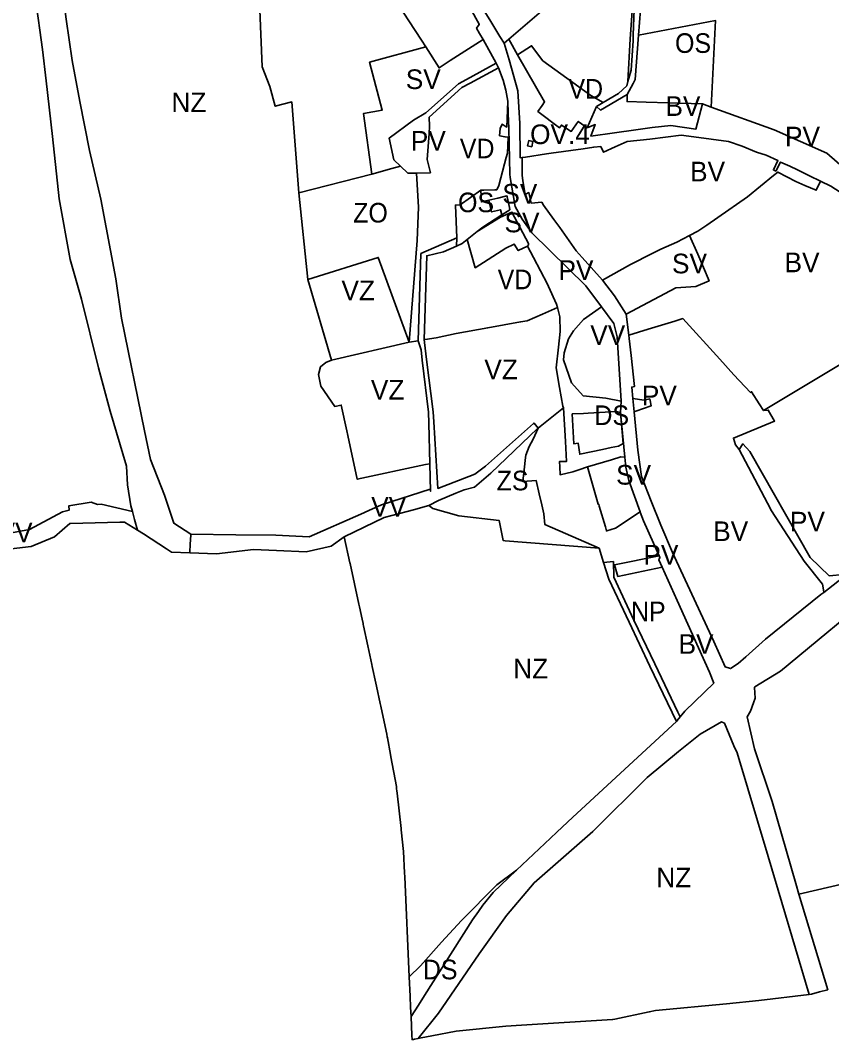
# Model space of a CAD drawing. Extents: x -650451 to -642268, y -1075216 to -1066610.
# Drawn here: x -645357 to -644737, y -1073665 to -1072886 of the extents above; entities that cross this region are included whole.
import ezdxf

# ---------------------------------------------------------------- set-up
doc = ezdxf.new("R2010")
doc.units = 0
doc.header["$LTSCALE"] = 6
doc.layers.add('1', color=7, linetype='Continuous', lineweight=35)
doc.layers.add('2', color=7, linetype='Continuous')
doc.layers.add('3', color=7, linetype='Continuous')

msp = doc.modelspace()

# ---------------------------------------------------------------- linework, layer by layer
at = {"layer": '1'}
for p, q in [((-645003.44, -1072900.56), (-644993.68, -1072918.61)), ((-644983.93, -1072900.24), (-644987.58, -1072903.38)), ((-644977.16, -1072912.11), (-644983.93, -1072900.24)), ((-644993.68, -1072918.61), (-644991.77, -1072922.13)), ((-644911.87, -1072948.76), (-644916.82, -1072951.76)), ((-644916.82, -1072951.76), (-644924, -1072967.87)), ((-644835.99, -1072949.74), (-644829.3, -1072952.16)), ((-645327.554, -1073022.214), (-645332.517, -1072974.538)), ((-645088.62, -1073003.45), (-645144.37, -1073017.64)), ((-645015.71, -1073053.41), (-645007.99, -1073047.31)), ((-645023.6, -1073052.12), (-645023.88, -1073058.37)), ((-645297.395, -1073151.294), (-645310.558, -1073098.946)), ((-644892.14, -1073126.36), (-644894.15, -1073110.3)), ((-644888.14, -1073184.92), (-644889.09, -1073174.81)), ((-644898.05, -1073176.78), (-644898.52, -1073185.53)), ((-644898.52, -1073185.53), (-644895.36, -1073219.51)), ((-645271.52, -1073261.16), (-645272.747, -1073256.762)), ((-644911.461, -1073299.98), (-644914.85, -1073289.05)), ((-644977.924, -1073535.072), (-644993.044, -1073546.324)), ((-644993.044, -1073546.324), (-645020.11, -1073573.585))]:
    msp.add_line(p, q, dxfattribs=at)
for points in [[(-645213.34, -1072669.98), (-645174.13, -1072877.93), (-645172.28, -1072921.42), (-645166.48, -1072936.5), (-645162.379, -1072951.55), (-645149.84, -1072948.13), (-645144.37, -1073017.64)], [(-645338.538, -1072746.821), (-645338.023, -1072755.969), (-645333.718, -1072799.987), (-645327.091, -1072848.387), (-645322.284, -1072885.085), (-645317.65, -1072916.642), (-645311.772, -1072947.945), (-645304.24, -1072985.372), (-645295.788, -1073022.556), (-645284.269, -1073083.286), (-645279.878, -1073113.356), (-645262.388, -1073199.409), (-645257.842, -1073221.36), (-645247.051, -1073248.736), (-645239.9, -1073270.025), (-645226.847, -1073278.345)], [(-644899.2, -1072762.14), (-644898.29, -1072766.55), (-644901.35, -1072785.36), (-644902.18, -1072797.88), (-644889.11, -1072871.66), (-644891.2, -1072900.09), (-644892.86, -1072932.6)], [(-644983.93, -1072900.24), (-644955.49, -1072875.78), (-644969.93, -1072861.43), (-644972.28, -1072859.02), (-644959.24, -1072844.92), (-644945.2, -1072826.3), (-644920.46, -1072792.92), (-644940.8, -1072781.48)], [(-645353.86, -1072794.339), (-645350.822, -1072830.388), (-645340.345, -1072908.029), (-645337.34, -1072932.073), (-645332.517, -1072974.538)], [(-645055.76, -1072816.4), (-645039.21, -1072842.26), (-645035.06, -1072848.67), (-645027.47, -1072860.37), (-645016.06, -1072878.67), (-645013.89, -1072877.29), (-645013.11, -1072876.8), (-645006.5, -1072888.88), (-645006.58, -1072889), (-645008.52, -1072891.76), (-645006.19, -1072895.8), (-645003.44, -1072900.56)], [(-645047.42, -1072906.05), (-645050.6, -1072901.03), (-645069.55, -1072872.12), (-645079.81, -1072855.89), (-645084.47, -1072825.67)], [(-644987.58, -1072903.38), (-644990.66, -1072898.22), (-644998.3, -1072885.43), (-645007.8, -1072870.27)], [(-644892.86, -1072932.6), (-644890.48, -1072924.04), (-644888.92, -1072901.64), (-644888.76, -1072897.07), (-644888.06, -1072877.6), (-644883.16, -1072877.92), (-644884.712, -1072897.147)], [(-644829.3, -1072952.16), (-644825.855, -1072886.074), (-644884.712, -1072897.147)], [(-645047.42, -1072906.05), (-645037.2, -1072922.24), (-645028.68, -1072916.54), (-645003.44, -1072900.56)], [(-644893.37, -1072942.61), (-644888.99, -1072934), (-644887.44, -1072930.94), (-644884.712, -1072897.147)], [(-645088.62, -1073003.45), (-645095.04, -1072957.07), (-645080.61, -1072954.43), (-645083.13, -1072944.94), (-645090.34, -1072917.86), (-645047.42, -1072906.05)], [(-644987.58, -1072903.38), (-644983.58, -1072915.92), (-644976.98, -1072939.7), (-644975.5, -1072964.62), (-644975.26, -1072990.9), (-644973.78, -1072990.67)], [(-644977.16, -1072912.11), (-644966.57, -1072905.23), (-644957.79, -1072916.73), (-644921.18, -1072943.17), (-644911.87, -1072948.76)], [(-644977.16, -1072912.11), (-644956.61, -1072948.16), (-644958.49, -1072950.87), (-644961.62, -1072955.39), (-644945.06, -1072967.89), (-644943.65, -1072965.85), (-644936.25, -1072970.76), (-644930.9, -1072963.08), (-644924, -1072967.87)], [(-645066.66, -1072997.3), (-645071.72, -1072992.52), (-645075.22, -1072975.8), (-645056.81, -1072962.13), (-645047.23, -1072956.57), (-645022.4, -1072934.31), (-645016.37, -1072931.01), (-644993.68, -1072918.61)], [(-644991.77, -1072922.13), (-645013.51, -1072933.92), (-645019.73, -1072937.29), (-645044.77, -1072959.83), (-645044.68, -1072961.82), (-645044.54, -1072964.66), (-645044.44, -1072966.73), (-645044.8, -1072972.22), (-645046.36, -1072992.1), (-645043.77, -1073002.3), (-645054.44, -1073002.54)], [(-644991.77, -1072922.13), (-644988.28, -1072931.51), (-644986.2, -1072939.16), (-644984.73, -1072947.56)], [(-644892.86, -1072932.6), (-644893.77, -1072935.88), (-644900.2, -1072941.67), (-644911.87, -1072948.76)], [(-645005.31, -1073015.68), (-645003.08, -1073015.61), (-644994.67, -1073015.36), (-644993.15, -1073015.31), (-644991.51, -1073012.16), (-644987.13, -1072995.44), (-644985.86, -1072990.55), (-644985.02, -1072987.36), (-644984.44, -1072975.19), (-644984.98, -1072975.1), (-644986.95, -1072974.75), (-644990.81, -1072974.08), (-644991.01, -1072974.02), (-644990.62, -1072968.58), (-644989.11, -1072965.25), (-644985.85, -1072967.18), (-644985.43, -1072967.43), (-644984.73, -1072947.56)], [(-644984.73, -1072947.56), (-644984.31, -1072957.08), (-644984, -1072968.31), (-644983.04, -1073003.33), (-644982.96, -1073006.06), (-644979.09, -1073027.97), (-644973.73, -1073037.82), (-644966.21, -1073048.32), (-644925.03, -1073088.75), (-644912.99, -1073104.65)], [(-644916.82, -1072951.76), (-644913.74, -1072954.38), (-644893.37, -1072942.61)], [(-644893.37, -1072942.61), (-644893.59, -1072947.97), (-644878.86, -1072948.42), (-644861.93, -1072948.94), (-644835.99, -1072949.74)], [(-644924, -1072967.87), (-644917.86, -1072965.55), (-644921.14, -1072974.47), (-644903.12, -1072971.8), (-644886.87, -1072969.46), (-644874.37, -1072967.75), (-644860.15, -1072966.28), (-644841.02, -1072969.02), (-644835.99, -1072949.74)], [(-644829.3, -1072952.16), (-644781.05, -1072969.61), (-644740.95, -1072987.23), (-644666.64, -1073051.97), (-644614.48, -1073096.25), (-644529.95, -1073158.06)], [(-644973.78, -1072990.67), (-644971.09, -1072990.31), (-644955.05, -1072987.8), (-644951.46, -1072987.25), (-644927.21, -1072984.16), (-644918.97, -1072982.7), (-644913.69, -1072982.13), (-644911.43, -1072986.59), (-644902.55, -1072982.55), (-644893.57, -1072978.46), (-644876.19, -1072976.67), (-644852.26, -1072973.62), (-644842.54, -1072974.93), (-644816.11, -1072978.51), (-644805.65, -1072981.92), (-644794.55, -1072986.49), (-644787.18, -1072988.95), (-644778.28, -1072993.06), (-644781.75, -1073000.11), (-644779.89, -1073001.07), (-644776.22, -1072994.18), (-644769.25, -1072997.23), (-644763.35, -1072999.96), (-644754.16, -1073004.6), (-644745.73, -1073008.64)], [(-644912.36, -1073084.42), (-644918.82, -1073077.02), (-644927.92, -1073066.94), (-644932.48, -1073061.9), (-644944.96, -1073044.2), (-644949.4, -1073038.05), (-644957.31, -1073027.07), (-644958.75, -1073024.7), (-644966.71, -1073025.57), (-644968.59, -1073017.44), (-644971.33, -1073018.81), (-644973.27, -1073008.52), (-644973.77, -1073004.25), (-644973.78, -1072990.67)], [(-645066.66, -1072997.3), (-645073.23, -1072999.05), (-645088.62, -1073003.45)], [(-645054.44, -1073002.54), (-645060.95, -1073002.68), (-645066.66, -1072997.3)], [(-645060.1, -1073131.68), (-645053.83, -1073054.04), (-645052.94, -1073028.58), (-645054.44, -1073002.54)], [(-644745.73, -1073008.64), (-644748.95, -1073015.64), (-644757.73, -1073012.05), (-644764.69, -1073008.87), (-644778.38, -1073001.84), (-644781.52, -1073004.39), (-644801.54, -1073020.61), (-644824.08, -1073036.56), (-644832.7, -1073042.34), (-644839.47, -1073046.89), (-644845.72, -1073050.14)], [(-644762.37, -1073553.42), (-644764.68, -1073545.3), (-644782.57, -1073482.57), (-644796.05, -1073442.48), (-644801.88, -1073417.95), (-644799.16, -1073413.58), (-644797.05, -1073407.39), (-644795.76, -1073403.59), (-644796.12, -1073395.56), (-644795.99, -1073395.08), (-644776.32, -1073383.08), (-644698.13, -1073318.48), (-644678.02, -1073303.11), (-644577.34, -1073226.12), (-644547.27, -1073203.12), (-644510.49, -1073173.7), (-644488.53, -1073156.12), (-644412.36, -1073110.27), (-644251.67, -1073006.23)], [(-644745.73, -1073008.64), (-644737.88, -1073012.62), (-644714.42, -1073027.62), (-644684.09, -1073050.8), (-644680.69, -1073053.67), (-644625.26, -1073099.51), (-644649.7, -1073116.65), (-644654.61, -1073120.1)], [(-645119.34, -1073145.61), (-645137.5, -1073083.97), (-645144.37, -1073017.64)], [(-645005.31, -1073015.68), (-645021.1, -1073026.69), (-645024.71, -1073026.95), (-645023.6, -1073052.12)], [(-644999.23, -1073023.29), (-645004.82, -1073024.63), (-645005.31, -1073015.68)], [(-645327.554, -1073022.214), (-645319.052, -1073068.6), (-645310.558, -1073098.946)], [(-644989.34, -1073034.58), (-644983.16, -1073030.56), (-644983.51, -1073028.9), (-644985.25, -1073020.72), (-644985.41, -1073019.98), (-644992.27, -1073021.63), (-644999.23, -1073023.29)], [(-644989.34, -1073034.58), (-644990.25, -1073030.54), (-644997.09, -1073032.21), (-644999.23, -1073023.29)], [(-645007.99, -1073047.31), (-644990.29, -1073036.36), (-644981.57, -1073032.3), (-644968.89, -1073056.23), (-644968.86, -1073057.45), (-644969.56, -1073058.48)], [(-645007.99, -1073047.31), (-645003.78, -1073043.96), (-644989.34, -1073034.58)], [(-644845.72, -1073050.14), (-644855.6, -1073055.26), (-644867.8, -1073060.76), (-644874.45, -1073064.02), (-644890.89, -1073072.33), (-644912.36, -1073084.42)], [(-644894.15, -1073110.3), (-644856.4, -1073090.13), (-644840.89, -1073089.3), (-644830.81, -1073084.98), (-644839.57, -1073064.5), (-644845.72, -1073050.14)], [(-645053.19, -1073130.59), (-645051.1, -1073064.11), (-645023.6, -1073052.12)], [(-645048.61, -1073129.7), (-645046.59, -1073065.77), (-645033.89, -1073062.8), (-645023.88, -1073058.37)], [(-645023.88, -1073058.37), (-645019.57, -1073056.46), (-645015.71, -1073053.41)], [(-645015.71, -1073053.41), (-645009.53, -1073074.93), (-644986.06, -1073059.87), (-644979.8, -1073056.82), (-644976.65, -1073061.82), (-644969.56, -1073058.48)], [(-644946.7, -1073105.33), (-644947.44, -1073102.73), (-644953.59, -1073089.19), (-644954.39, -1073087.42), (-644964.98, -1073067.05), (-644969.56, -1073058.48)], [(-645137.5, -1073083.97), (-645083.681, -1073066.962), (-645060.1, -1073131.68)], [(-644894.15, -1073110.3), (-644903.22, -1073096.43), (-644912.36, -1073084.42)], [(-644912.99, -1073104.65), (-644926.77, -1073114.52), (-644934.41, -1073123.05), (-644938.32, -1073129.23), (-644941.63, -1073139.89), (-644942.07, -1073145.31), (-644936.06, -1073162.79), (-644927.05, -1073172.62), (-644909.83, -1073174.51), (-644898.05, -1073176.78)], [(-644912.99, -1073104.65), (-644903.72, -1073117.41), (-644901.2, -1073127.58), (-644898.05, -1073176.78)], [(-645048.61, -1073129.7), (-645047.73, -1073129.58), (-645039.47, -1073128.42), (-645024.04, -1073125.1), (-645000.03, -1073120.76), (-644974.89, -1073116.24), (-644969.91, -1073115.34), (-644958.27, -1073110.25), (-644946.7, -1073105.33)], [(-644946.7, -1073105.33), (-644945, -1073112.3), (-644944.63, -1073123.59), (-644945.99, -1073135.51), (-644947.8, -1073151.31), (-644945.13, -1073166.37), (-644942.58, -1073180.69), (-644942.17, -1073181.78)], [(-644789.31, -1073183.93), (-644663.17, -1073108.27), (-644656.56, -1073117.4), (-644654.61, -1073120.1)], [(-644892.14, -1073126.36), (-644877.32, -1073121.83), (-644856.97, -1073115.6), (-644851, -1073113.77), (-644822.62, -1073144.71), (-644811.96, -1073156.75), (-644799.26, -1073170.13), (-644798.38, -1073169.56), (-644792.59, -1073178.73), (-644789.31, -1073183.93)], [(-644889.09, -1073174.81), (-644889.93, -1073166), (-644887.77, -1073165.6), (-644890.43, -1073142), (-644891.87, -1073128.85), (-644892.14, -1073126.36)], [(-645119.34, -1073145.61), (-645060.1, -1073131.68), (-645053.19, -1073130.59)], [(-645053.19, -1073130.59), (-645052.45, -1073132.97), (-645050.98, -1073137.65), (-645050.1, -1073145.42), (-645045.31, -1073185.17), (-645045.08, -1073193.68), (-645044.246, -1073224.619)], [(-645048.61, -1073129.7), (-645048.32, -1073132.07), (-645046.72, -1073145.03), (-645041.81, -1073184.95), (-645041.32, -1073192.66), (-645038.11, -1073243.46), (-645010, -1073232.5), (-645001.8, -1073226.39), (-644965.03, -1073193.94), (-644964.55, -1073193.54), (-644961.44, -1073197.35)], [(-645297.395, -1073151.294), (-645288.647, -1073184.518), (-645276.125, -1073226.571), (-645275.269, -1073240.71), (-645272.747, -1073256.762)], [(-645119.34, -1073145.61), (-645123.616, -1073147.195), (-645127.781, -1073150.527), (-645129.447, -1073156.525), (-645127.615, -1073165.356), (-645116.951, -1073180.851), (-645111.98, -1073179.822), (-645107.76, -1073199.45), (-645107.02, -1073202.91), (-645099.78, -1073236.52), (-645047.59, -1073225.3), (-645044.246, -1073224.619)], [(-644889.09, -1073174.81), (-644880.45, -1073176.07), (-644876.22, -1073175.09), (-644875.1, -1073180.36), (-644886.75, -1073184.43), (-644888.14, -1073184.92)], [(-644961.44, -1073197.35), (-644959.91, -1073196.15), (-644942.17, -1073181.78)], [(-644923.88, -1073227.01), (-644930.46, -1073229.16), (-644934.87, -1073230.72), (-644944.7, -1073233.01), (-644945.03, -1073226.98), (-644945.25, -1073223.01), (-644939.95, -1073223), (-644940.47, -1073207.57), (-644942.17, -1073181.78)], [(-644888.14, -1073184.92), (-644885.36, -1073214.3), (-644882.44, -1073234.39), (-644875.09, -1073253.22), (-644867.69, -1073271.42), (-644858.88, -1073292.32), (-644855.75, -1073299.15), (-644827.23, -1073360.35), (-644818.67, -1073379.69), (-644814.49, -1073381.06), (-644808.69, -1073377.3), (-644802.84, -1073372.09), (-644787.75, -1073358.68), (-644745.44, -1073324.48), (-644743.23, -1073322.94)], [(-644808.01, -1073213.67), (-644810.56, -1073210.15), (-644812.29, -1073205.05), (-644780.87, -1073191.97), (-644785.72, -1073183.67), (-644789.31, -1073183.93)], [(-644961.44, -1073197.35), (-644961.91, -1073197.75), (-644997.71, -1073231.77), (-645010.2, -1073242.6), (-645017.98, -1073244.63), (-645024.51, -1073247.07), (-645037.53, -1073252.62), (-645045, -1073256.54)], [(-644961.44, -1073197.35), (-644965.42, -1073205.74), (-644968.33, -1073211.34), (-644970.84, -1073218.02), (-644971.04, -1073219.75), (-644972.09, -1073229.15), (-644973.32, -1073238.15), (-644963.08, -1073237.3), (-644960.75, -1073247.57), (-644958.74, -1073256.06), (-644957.14, -1073262.81), (-644956.39, -1073270.99), (-644914.85, -1073289.05)], [(-644725.21, -1073308.93), (-644728.18, -1073309.21), (-644738.99, -1073310.21), (-644753.67, -1073296.24), (-644799.84, -1073215.22), (-644805.08, -1073209.3), (-644808.01, -1073213.67)], [(-644808.01, -1073213.67), (-644786.28, -1073254.69), (-644783.14, -1073260.62), (-644758.33, -1073299.16), (-644744.17, -1073316.51), (-644743.51, -1073321), (-644743.23, -1073322.94)], [(-644923.88, -1073227.01), (-644905.47, -1073221.56), (-644898.37, -1073219.42), (-644895.36, -1073219.51)], [(-644895.36, -1073219.51), (-644894.44, -1073227.29), (-644892.09, -1073237.34), (-644883.55, -1073261.27)], [(-645226.847, -1073278.345), (-645192.45, -1073278.84), (-645161.91, -1073279.24), (-645136.55, -1073280.36), (-645096.96, -1073263.01), (-645090.9, -1073260.31), (-645081.07, -1073256.01), (-645043.97, -1073244.09), (-645043.68, -1073245.61), (-645044.246, -1073224.619)], [(-644883.55, -1073261.27), (-644902.28, -1073273.73), (-644909.03, -1073275.83), (-644909.38, -1073275.94), (-644910.11, -1073272.74), (-644914.78, -1073257.12), (-644915.24, -1073255.45), (-644915.63, -1073255.56), (-644923.88, -1073227.01)], [(-645271.52, -1073261.16), (-645295.44, -1073255.48), (-645298.27, -1073255.65), (-645302.963, -1073253.878), (-645320.244, -1073256.876), (-645319.96, -1073260.12), (-645325.07, -1073261.39), (-645350.08, -1073274.88), (-645389.08, -1073281.94), (-645404.03, -1073288.01), (-645427.83, -1073301.03), (-645457.38, -1073313.78), (-645476.1, -1073316.93), (-645499.41, -1073318.24)], [(-645109.6, -1073280.56), (-645079.12, -1073265.63), (-645061.7, -1073261.22), (-645056.82, -1073259.85), (-645045, -1073256.54)], [(-645045, -1073256.54), (-645042.08, -1073258.81), (-645022.07, -1073264.52), (-644991.26, -1073268.06), (-644988.14, -1073283.32), (-644986.64, -1073283.44), (-644914.85, -1073289.05)], [(-645271.52, -1073261.16), (-645269.83, -1073267.22), (-645267.53, -1073275.44)], [(-644883.55, -1073261.27), (-644883.45, -1073261.55), (-644880.99, -1073268.25), (-644868.95, -1073294.94)], [(-645499.41, -1073318.24), (-645492.7, -1073323.51), (-645492.16, -1073323.95), (-645459.78, -1073326.21), (-645442.26, -1073319.33), (-645431.37, -1073313.2), (-645414.6, -1073312.83), (-645381.21, -1073286.79), (-645364.15, -1073289.58), (-645348.9, -1073287.85), (-645331.05, -1073280.34), (-645319.42, -1073270.28), (-645318.94, -1073270.27), (-645281.1, -1073269.26), (-645277.57, -1073269.17), (-645267.53, -1073275.44)], [(-645227.744, -1073292.736), (-645241.72, -1073292.2), (-645245.5, -1073289.73), (-645263.03, -1073278.25), (-645267.53, -1073275.44)], [(-645226.847, -1073278.345), (-645227.199, -1073283.366), (-645227.35, -1073285.55), (-645227.744, -1073292.736)], [(-645227.744, -1073292.736), (-645207.27, -1073293.52), (-645179.11, -1073290.25), (-645161.51, -1073290.8), (-645138.82, -1073291.94), (-645119.56, -1073287.5), (-645109.6, -1073280.56)], [(-645060.01, -1073616.531), (-645063.42, -1073540.09), (-645063.55, -1073537.04), (-645064.28, -1073520.73), (-645066.11, -1073504.38), (-645066.22, -1073503.38), (-645069.27, -1073476.16), (-645069.45, -1073474.51), (-645069.63, -1073472.94), (-645069.82, -1073471.22), (-645074, -1073448.52), (-645074.34, -1073446.7), (-645076.69, -1073433.94), (-645076.81, -1073433.27), (-645077.19, -1073431.24), (-645078.27, -1073425.38), (-645081.62, -1073409.9), (-645082.11, -1073407.66), (-645084.96, -1073394.48), (-645085.46, -1073392.18), (-645088.22, -1073379.41), (-645088.5, -1073378.1), (-645091.62, -1073363.7), (-645094.92, -1073348.42), (-645095.12, -1073347.53), (-645095.32, -1073346.61), (-645096.01, -1073343.4), (-645098.07, -1073333.86), (-645098.51, -1073331.86), (-645105.21, -1073300.86), (-645105.33, -1073300.32), (-645109.6, -1073280.56)], [(-644852.94, -1073418.04), (-644854.72, -1073414.33), (-644872.35, -1073377.53), (-644888.29, -1073344), (-644903.66, -1073311.34), (-644903.92, -1073299.4), (-644911.461, -1073299.98)], [(-644866.71, -1073303.59), (-644900.48, -1073310.67), (-644903.12, -1073301.88), (-644868.95, -1073294.94)], [(-644868.95, -1073294.94), (-644868.42, -1073296.11), (-644869.21, -1073298.06), (-644866.71, -1073303.59)], [(-644911.461, -1073299.98), (-644907.47, -1073312.85), (-644891.94, -1073345.72), (-644876.05, -1073379.3), (-644855.81, -1073421.57)], [(-644866.71, -1073303.59), (-644855.23, -1073329.01), (-644838.85, -1073365.29), (-644830.43, -1073383.91), (-644827.25, -1073392.29), (-644834.38, -1073399.18), (-644849.42, -1073413.72), (-644852.94, -1073418.04)], [(-644743.23, -1073322.94), (-644728.83, -1073311.71), (-644725.21, -1073308.93)], [(-644762.37, -1073553.42), (-644452.17, -1073481.3), (-644372.58, -1073462.83), (-644363.26, -1073460.66), (-644189.82, -1073420.36), (-643971.48, -1073369.61), (-643951.41, -1073364.95)], [(-644754.41, -1073629.99), (-644785.78, -1073524.66), (-644809.35, -1073445.51), (-644811.95, -1073440), (-644819.19, -1073422.9), (-644821.51, -1073421.83), (-644837.65, -1073431.13), (-644854.34, -1073444.4), (-644878.09, -1073464.33), (-644919.6, -1073505.63), (-644964.57, -1073544.75), (-644985.78, -1073569.64), (-645006.55, -1073599.09), (-645037.66, -1073644.42), (-645053.13, -1073663.63)], [(-644855.81, -1073421.57), (-644934.91, -1073494.57), (-644947.18, -1073506.06), (-644952.02, -1073510.63), (-644977.924, -1073535.072)], [(-644852.94, -1073418.04), (-644855.22, -1073420.84), (-644855.81, -1073421.57)], [(-644977.924, -1073535.072), (-644995.96, -1073552.09), (-645003.83, -1073561.94), (-645007.1, -1073566.62), (-645011.61, -1073573.07), (-645048.32, -1073630.82), (-645053.02, -1073638.21), (-645058.65, -1073647)], [(-644754.41, -1073629.99), (-644752.73, -1073629.78), (-644746.45, -1073628.1), (-644740.13, -1073626.4), (-644762.37, -1073553.42)], [(-645020.11, -1073573.585), (-645035.303, -1073590.199), (-645051.513, -1073608.124), (-645060.01, -1073616.531)], [(-645060.01, -1073616.531), (-645059.35, -1073631.3), (-645058.96, -1073640.09), (-645058.65, -1073647)], [(-645053.13, -1073663.63), (-645050.98, -1073663.21), (-645042.62, -1073661.59), (-645024.12, -1073658.01), (-644986.25, -1073654.32), (-644974.31, -1073653.58), (-644904.61, -1073649.23), (-644902.83, -1073648.86), (-644876.58, -1073643.43), (-644871.71, -1073642.42), (-644817.66, -1073637.16), (-644792.87, -1073634.74), (-644754.41, -1073629.99)], [(-645058.65, -1073647), (-645058.01, -1073661.37), (-645057.87, -1073664.55), (-645056.8, -1073664.34), (-645056.06, -1073664.2), (-645053.13, -1073663.63)]]:
    msp.add_lwpolyline(points, dxfattribs=at)
for points in [[(-644966.3, -1072982.52), (-644965.48, -1072978.36), (-644968.65, -1072977.73), (-644969.52, -1072981.84)], [(-644898.52, -1073185.53), (-644896.55, -1073209.03), (-644900.12, -1073211.08), (-644905.66, -1073212.26), (-644912.32, -1073213.69), (-644929.76, -1073217.37), (-644930.88, -1073209), (-644934.12, -1073209.43), (-644935.46, -1073186.49), (-644926.89, -1073186.2), (-644923.24, -1073186.09), (-644901.52, -1073184.68)]]:
    msp.add_lwpolyline(points, close=True, dxfattribs=at)

# ---------------------------------------------------------------- texts
at = {"layer": '2'}
for s, p in [('SV', (-645062.664, -1072938.359)), ('NZ', (-645241.75, -1072955.998)), ('BV', (-644864.224, -1072958.873)), ('PV', (-645058.812, -1072985.424)), ('OV.4', (-644967.656, -1072980.409)), ('PV', (-644772.857, -1072982.18)), ('BV', (-644845.4, -1073008.87)), ('SV', (-644988.867, -1073025.824)), ('SV', (-644987.205, -1073047.806)), ('SV', (-644859.23, -1073079.16)), ('PV', (-644945.986, -1073084.171)), ('VV', (-644921.66, -1073133.779)), ('VZ', (-645002.62, -1073160.061)), ('VZ', (-645089.324, -1073175.623)), ('PV', (-644882.256, -1073179.951)), ('SV', (-644901.955, -1073240.564)), ('VV', (-645089.058, -1073265.048)), ('BV', (-644827.725, -1073283.663)), ('PV', (-644769.119, -1073276.348)), ('VV', (-645374.566, -1073284.589)), ('PV', (-644881.073, -1073301.684)), ('BV', (-644854.22, -1073369.818)), ('NZ', (-644980.553, -1073388.616)), ('NZ', (-644871.198, -1073548.215))]:
    msp.add_text(s, height=15, dxfattribs=at).set_placement(p)
at = {"layer": '2', "width": 0.95}
for s, p in [('VD', (-644938.333, -1072945.706)), ('VD', (-645021.332, -1072991.282)), ('VD', (-644992.431, -1073091.325)), ('DS', (-644918.487, -1073195.028)), ('ZS', (-644993.178, -1073244.944)), ('NP', (-644890.556, -1073344.948))]:
    msp.add_text(s, height=15, dxfattribs=at).set_placement(p)
at = {"layer": '3', "width": 0.95}
for s, p in [('OS', (-644856.888, -1072910.746)), ('OS', (-645022.705, -1073032.46)), ('ZO', (-645102.821, -1073040.324)), ('DS', (-645049.609, -1073618.488))]:
    msp.add_text(s, height=15, dxfattribs=at).set_placement(p)
at = {"layer": '3'}
for s, p in [('BV', (-644773.212, -1073078.301)), ('VZ', (-645111.811, -1073099.727))]:
    msp.add_text(s, height=15, dxfattribs=at).set_placement(p)

doc.saveas('drawing.dxf')
